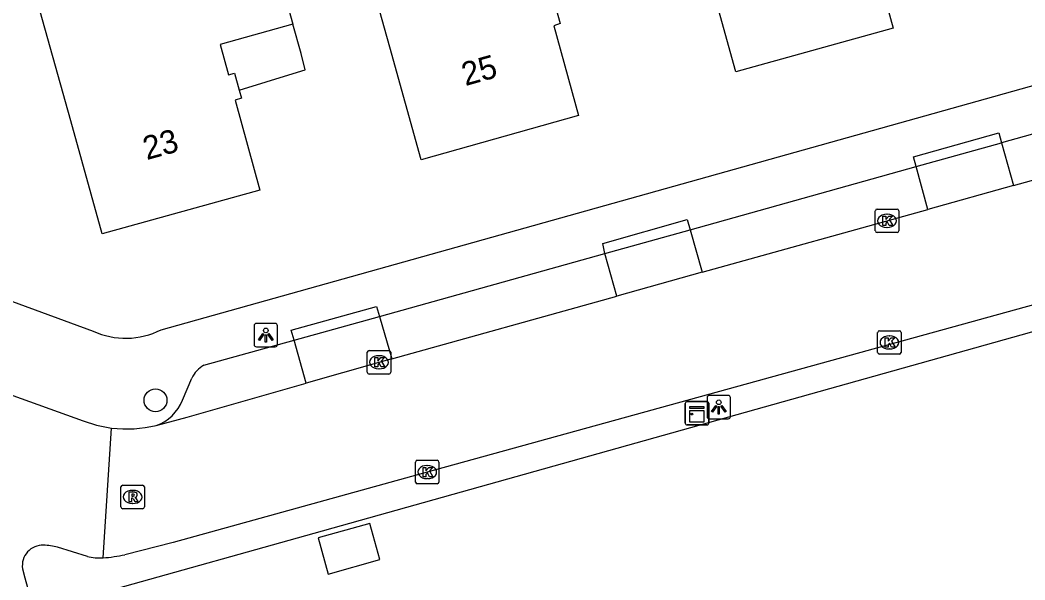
# Model space of a CAD drawing. Extents: x 159628 to 160723, y 388176 to 389416.
# Drawn here: x 159913.26 to 159956.19, y 388453.52 to 388477.42 of the extents above; entities that cross this region are included whole.
import ezdxf

# ---------------------------------------------------------------- set-up
doc = ezdxf.new("R2010")
doc.units = 0
for name, color, linetype in [('IMGEO_Boom', 7, 'Continuous'), ('IMGEO_Kast', 7, 'Continuous'), ('IMGEO_Kolk', 7, 'Continuous'), ('IMGEO_Lichtpunt', 7, 'Continuous'), ('IMGEO_Muur', 7, 'Continuous'), ('IMGEO_Pand', 7, 'Continuous'), ('IMGEO_Pand_nummerreeks', 7, 'Continuous'), ('IMGEO_Pand_overbouw', 7, 'Continuous'), ('IMGEO_Parkeervlak_open', 7, 'Continuous'), ('IMGEO_Rijbaan_lokaal_open', 7, 'Continuous'), ('IMGEO_Rioolput', 7, 'Continuous'), ('IMGEO_Voetpad_open', 7, 'Continuous')]:
    doc.layers.add(name, color=color, linetype=linetype)

msp = doc.modelspace()

# ---------------------------------------------------------------- linework, layer by layer
at = {"layer": 'IMGEO_Boom'}
msp.add_circle((159919.046, 388461.193), 0.489, dxfattribs=at)
at = {"layer": 'IMGEO_Kast'}
for p, q in [((159941.683, 388460.213), (159941.683, 388461.054)), ((159941.683, 388461.054), (159941.683, 388460.213)), ((159941.758, 388461.138), (159942.599, 388461.138)), ((159942.599, 388461.138), (159941.758, 388461.138)), ((159942.683, 388461.063), (159942.683, 388460.222)), ((159942.683, 388460.222), (159942.683, 388461.063)), ((159942.608, 388460.138), (159941.767, 388460.138)), ((159941.767, 388460.138), (159942.608, 388460.138))]:
    msp.add_line(p, q, dxfattribs=at)
for points in [[(159941.878, 388460.928), (159942.478, 388460.928), (159942.478, 388460.843), (159941.878, 388460.843), (159941.878, 388460.928)], [(159941.878, 388460.753), (159942.478, 388460.753), (159942.478, 388460.264), (159941.878, 388460.264), (159941.878, 388460.753)]]:
    msp.add_lwpolyline(points, dxfattribs=at)
msp.add_circle((159941.962, 388460.602), 0.0377, dxfattribs=at)
for centre, start, end in [((159941.761, 388461.06), 92.4484, 184.2845), ((159941.761, 388461.06), 92.4484, 184.2845), ((159942.605, 388461.06), 2.4484, 94.2845), ((159942.605, 388461.06), 2.4484, 94.2845), ((159941.761, 388460.216), 182.4484, 274.2845), ((159941.761, 388460.216), 182.4484, 274.2845), ((159942.605, 388460.216), 272.4484, 4.2845), ((159942.605, 388460.216), 272.4484, 4.2845)]:
    msp.add_arc(centre, 0.0779, start, end, dxfattribs=at)
at = {"layer": 'IMGEO_Kolk'}
for p, q in [((159949.876, 388469.354), (159950.728, 388469.354)), ((159949.801, 388468.428), (159949.801, 388469.28)), ((159950.289, 388469.134), (159950.314, 388469.134)), ((159950.802, 388469.28), (159950.802, 388468.428)), ((159950.312, 388468.574), (159950.287, 388468.574)), ((159950.728, 388468.354), (159949.876, 388468.354)), ((159949.901, 388463.237), (159949.901, 388464.089)), ((159949.976, 388464.163), (159950.828, 388464.163)), ((159950.389, 388463.943), (159950.414, 388463.943)), ((159950.902, 388464.089), (159950.902, 388463.237)), ((159950.412, 388463.383), (159950.387, 388463.383)), ((159928.095, 388462.387), (159928.095, 388463.239)), ((159928.17, 388463.313), (159929.022, 388463.313)), ((159928.583, 388463.093), (159928.608, 388463.093)), ((159929.096, 388463.239), (159929.096, 388462.387)), ((159950.828, 388463.163), (159949.976, 388463.163)), ((159928.606, 388462.533), (159928.581, 388462.533)), ((159929.022, 388462.313), (159928.17, 388462.313)), ((159930.232, 388458.629), (159931.084, 388458.629)), ((159930.157, 388457.703), (159930.157, 388458.555)), ((159930.645, 388458.409), (159930.67, 388458.409)), ((159931.158, 388458.555), (159931.158, 388457.703)), ((159930.668, 388457.849), (159930.643, 388457.849)), ((159931.084, 388457.629), (159930.232, 388457.629))]:
    msp.add_line(p, q, dxfattribs=at)
for points in [[(159949.876, 388469.354), (159950.728, 388469.354)], [(159949.801, 388468.428), (159949.801, 388469.28)], [(159950.122, 388469.054), (159950.245, 388469.054), (159950.245, 388468.903), (159950.375, 388469.054), (159950.539, 388469.054), (159950.393, 388468.903), (159950.546, 388468.654), (159950.394, 388468.654), (159950.309, 388468.818), (159950.245, 388468.751), (159950.245, 388468.654), (159950.122, 388468.654), (159950.122, 388469.054)], [(159950.802, 388469.28), (159950.802, 388468.428)], [(159950.728, 388468.354), (159949.876, 388468.354)], [(159949.901, 388463.237), (159949.901, 388464.089)], [(159949.976, 388464.163), (159950.828, 388464.163)], [(159950.222, 388463.863), (159950.345, 388463.863), (159950.345, 388463.712), (159950.475, 388463.863), (159950.639, 388463.863), (159950.493, 388463.712), (159950.646, 388463.463), (159950.494, 388463.463), (159950.409, 388463.627), (159950.345, 388463.56), (159950.345, 388463.463), (159950.222, 388463.463), (159950.222, 388463.863)], [(159950.902, 388464.089), (159950.902, 388463.237)], [(159928.095, 388462.387), (159928.095, 388463.239)], [(159928.17, 388463.313), (159929.022, 388463.313)], [(159928.416, 388463.013), (159928.539, 388463.013), (159928.539, 388462.862), (159928.669, 388463.013), (159928.833, 388463.013), (159928.687, 388462.862), (159928.84, 388462.613), (159928.688, 388462.613), (159928.603, 388462.777), (159928.539, 388462.71), (159928.539, 388462.613), (159928.416, 388462.613), (159928.416, 388463.013)], [(159929.096, 388463.239), (159929.096, 388462.387)], [(159950.828, 388463.163), (159949.976, 388463.163)], [(159929.022, 388462.313), (159928.17, 388462.313)], [(159930.232, 388458.629), (159931.084, 388458.629)], [(159930.157, 388457.703), (159930.157, 388458.555)], [(159930.478, 388458.329), (159930.601, 388458.329), (159930.601, 388458.178), (159930.731, 388458.329), (159930.895, 388458.329), (159930.749, 388458.178), (159930.902, 388457.929), (159930.75, 388457.929), (159930.665, 388458.093), (159930.601, 388458.026), (159930.601, 388457.929), (159930.478, 388457.929), (159930.478, 388458.329)], [(159931.158, 388458.555), (159931.158, 388457.703)], [(159931.084, 388457.629), (159930.232, 388457.629)]]:
    msp.add_lwpolyline(points, dxfattribs=at)
for centre, start, end in [((159949.878, 388469.278), 91.552, 178.448), ((159949.878, 388469.278), 91.552, 178.448), ((159950.726, 388469.278), 1.552, 88.448), ((159950.726, 388469.278), 1.552, 88.448), ((159949.878, 388468.43), 181.552, 268.448), ((159949.878, 388468.43), 181.552, 268.448), ((159950.726, 388468.43), 271.552, 358.448), ((159950.726, 388468.43), 271.552, 358.448), ((159949.978, 388464.087), 91.552, 178.448), ((159949.978, 388464.087), 91.552, 178.448), ((159950.826, 388464.087), 1.552, 88.448), ((159950.826, 388464.087), 1.552, 88.448), ((159928.172, 388463.237), 91.552, 178.448), ((159928.172, 388463.237), 91.552, 178.448), ((159929.02, 388463.237), 1.552, 88.448), ((159929.02, 388463.237), 1.552, 88.448), ((159949.978, 388463.239), 181.552, 268.448), ((159949.978, 388463.239), 181.552, 268.448), ((159950.826, 388463.239), 271.552, 358.448), ((159950.826, 388463.239), 271.552, 358.448), ((159928.172, 388462.389), 181.552, 268.448), ((159928.172, 388462.389), 181.552, 268.448), ((159929.02, 388462.389), 271.552, 358.448), ((159929.02, 388462.389), 271.552, 358.448), ((159930.234, 388458.553), 91.552, 178.448), ((159930.234, 388458.553), 91.552, 178.448), ((159931.082, 388458.553), 1.552, 88.448), ((159931.082, 388458.553), 1.552, 88.448), ((159930.234, 388457.705), 181.552, 268.448), ((159930.234, 388457.705), 181.552, 268.448), ((159931.082, 388457.705), 271.552, 358.448), ((159931.082, 388457.705), 271.552, 358.448)]:
    msp.add_arc(centre, 0.0765, start, end, dxfattribs=at)
for centre, major_axis, ratio, start_param, end_param in [((159950.288, 388468.854), (-0.387, 0.002), 0.722429, 4.712389, 7.853982), ((159950.313, 388468.854), (-0.39, 0.002), 0.717154, 1.570796, 4.712389), ((159950.388, 388463.663), (-0.387, 0.002), 0.722429, 4.712389, 7.853982), ((159950.413, 388463.663), (-0.39, 0.002), 0.717154, 1.570796, 4.712389), ((159928.582, 388462.813), (-0.387, 0.002), 0.722429, 4.712389, 7.853982), ((159928.607, 388462.813), (-0.39, 0.002), 0.717154, 1.570796, 4.712389), ((159930.644, 388458.129), (-0.387, 0.002), 0.722429, 4.712389, 7.853982), ((159930.669, 388458.129), (-0.39, 0.002), 0.717154, 1.570796, 4.712389)]:
    msp.add_ellipse(centre, major_axis=major_axis, ratio=ratio, start_param=start_param, end_param=end_param, dxfattribs=at)
at = {"layer": 'IMGEO_Lichtpunt'}
for p, q in [((159923.261, 388464.376), (159923.261, 388463.569)), ((159923.261, 388464.376), (159923.261, 388463.569)), ((159924.163, 388464.471), (159923.355, 388464.471)), ((159924.163, 388464.471), (159923.355, 388464.471)), ((159924.257, 388463.569), (159924.257, 388464.376)), ((159924.257, 388463.569), (159924.257, 388464.376)), ((159923.355, 388463.475), (159924.163, 388463.475)), ((159923.355, 388463.475), (159924.163, 388463.475)), ((159942.613, 388461.307), (159942.613, 388460.5)), ((159942.613, 388461.307), (159942.613, 388460.5)), ((159943.515, 388461.402), (159942.707, 388461.402)), ((159943.515, 388461.402), (159942.707, 388461.402)), ((159943.609, 388460.5), (159943.609, 388461.307)), ((159943.609, 388460.5), (159943.609, 388461.307)), ((159942.707, 388460.406), (159943.515, 388460.406)), ((159942.707, 388460.406), (159943.515, 388460.406))]:
    msp.add_line(p, q, dxfattribs=at)
for points in [[(159923.635, 388464.04), (159923.674, 388464.012), (159923.486, 388463.75), (159923.448, 388463.777), (159923.635, 388464.04)], [(159923.737, 388463.992), (159923.784, 388463.992), (159923.784, 388463.67), (159923.737, 388463.67), (159923.737, 388463.992)], [(159923.847, 388464.012), (159923.885, 388464.039), (159924.072, 388463.777), (159924.033, 388463.749), (159923.847, 388464.012)], [(159942.987, 388460.971), (159943.026, 388460.943), (159942.838, 388460.681), (159942.8, 388460.708), (159942.987, 388460.971)], [(159943.089, 388460.923), (159943.136, 388460.923), (159943.136, 388460.601), (159943.089, 388460.601), (159943.089, 388460.923)], [(159943.199, 388460.943), (159943.237, 388460.97), (159943.424, 388460.708), (159943.385, 388460.68), (159943.199, 388460.943)]]:
    msp.add_lwpolyline(points, dxfattribs=at)
for centre in [(159923.76, 388464.174), (159943.112, 388461.105)]:
    msp.add_circle(centre, 0.0994, dxfattribs=at)
for centre, start, end in [((159923.355, 388464.376), 90, 180), ((159923.355, 388464.376), 90, 180), ((159924.163, 388464.376), 0, 90), ((159924.163, 388464.376), 0, 90), ((159923.355, 388463.569), 180, 270), ((159923.355, 388463.569), 180, 270), ((159924.163, 388463.569), 270, 0), ((159924.163, 388463.569), 270, 360), ((159942.707, 388461.307), 90, 180), ((159942.707, 388461.307), 90, 180), ((159943.515, 388461.307), 0, 90), ((159943.515, 388461.307), 0, 90), ((159942.707, 388460.5), 180, 270), ((159942.707, 388460.5), 180, 270), ((159943.515, 388460.5), 270, 0), ((159943.515, 388460.5), 270, 360)]:
    msp.add_arc(centre, 0.0946, start, end, dxfattribs=at)
at = {"layer": 'IMGEO_Muur'}
msp.add_lwpolyline([(159925.832, 388455.524), (159959.997, 388465.092)], dxfattribs=at)
at = {"layer": 'IMGEO_Pand'}
for points in [[(159950.64, 388488.978), (159951.972, 388484.158), (159948.858, 388483.298), (159949.217, 388481.996), (159949.477, 388482.067), (159949.678, 388481.342), (159949.772, 388481.002), (159949.508, 388480.912), (159950.557, 388477.077), (159943.837, 388475.221), (159942.502, 388480.04), (159940.985, 388485.514), (159944.105, 388486.378), (159942.931, 388490.615), (159949.672, 388492.483), (159950.64, 388488.978)], [(159938.532, 388480.412), (159935.434, 388479.557), (159935.793, 388478.255), (159936.053, 388478.326), (159936.243, 388477.64), (159936.342, 388477.283), (159936.058, 388477.184), (159937.126, 388473.343), (159930.4, 388471.458), (159929.055, 388476.274), (159927.523, 388481.761), (159930.649, 388482.634), (159929.467, 388486.866), (159936.2, 388488.746), (159937.184, 388485.228), (159938.532, 388480.412)], [(159923.574, 388482.06), (159924.919, 388477.244), (159921.805, 388476.384), (159922.164, 388475.082), (159922.424, 388475.153), (159922.625, 388474.428), (159922.719, 388474.088), (159922.455, 388473.998), (159923.504, 388470.163), (159916.769, 388468.303), (159915.425, 388473.12), (159913.89, 388478.62), (159917.021, 388479.496), (159915.84, 388483.716), (159922.584, 388485.604), (159923.574, 388482.06)], [(159925.991, 388455.313), (159926.424, 388453.769), (159928.635, 388454.389), (159928.202, 388455.933), (159925.991, 388455.313)]]:
    msp.add_lwpolyline(points, dxfattribs=at)
at = {"layer": 'IMGEO_Pand_overbouw'}
msp.add_lwpolyline([(159922.625, 388474.428), (159924.925, 388475.148), (159925.435, 388475.298), (159925.263, 388475.998), (159924.919, 388477.244), (159921.805, 388476.384), (159922.164, 388475.082), (159922.424, 388475.153)], close=True, dxfattribs=at)
at = {"layer": 'IMGEO_Parkeervlak_open'}
for points in [[(159955.198, 388472.186), (159955.708, 388470.358)], [(159952.05, 388469.34), (159951.542, 388471.166)], [(159941.895, 388468.474), (159942.401, 388466.655)], [(159938.754, 388465.64), (159938.248, 388467.459)], [(159928.622, 388464.774), (159929.138, 388462.964)], [(159925.486, 388461.926), (159924.964, 388463.756)]]:
    msp.add_lwpolyline(points, dxfattribs=at)
at = {"layer": 'IMGEO_Rijbaan_lokaal_open'}
for points in [[(159955.708, 388470.358), (159962.432, 388472.229)], [(159955.708, 388470.358), (159952.05, 388469.34)], [(159942.401, 388466.655), (159952.05, 388469.34)], [(159963.841, 388467.276), (159930.654, 388458.13), (159919.806, 388455.118), (159917.73, 388454.597)], [(159942.401, 388466.655), (159938.754, 388465.64)], [(159929.138, 388462.964), (159938.754, 388465.64)], [(159909.074, 388462.915), (159909.569, 388462.607), (159915.949, 388460.312), (159916.527, 388460.133), (159917.172, 388460.006)], [(159929.138, 388462.964), (159928.592, 388462.812), (159925.486, 388461.926)], [(159919.075, 388460.117), (159920.394, 388460.474), (159925.486, 388461.926)], [(159916.812, 388454.464), (159917.172, 388460.006)], [(159916.136, 388454.528), (159914.865, 388454.92)], [(159913.366, 388454.001), (159913.457, 388453.607), (159913.858, 388452.179)]]:
    msp.add_lwpolyline(points, dxfattribs=at)
for centre, radius, start, end in [((159917.813, 388465.378), 5.41, 263.1913, 283.4852), ((159914.218, 388454.142), 0.863, 87.0578, 189.3921), ((159914.138, 388451.907), 3.099, 76.4326, 87.7064), ((159916.671, 388456.579), 2.12, 255.3755, 273.8079), ((159916.141, 388462.329), 7.894, 274.8754, 281.6119)]:
    msp.add_arc(centre, radius, start, end, dxfattribs=at)
at = {"layer": 'IMGEO_Rioolput'}
for p, q in [((159917.57, 388456.638), (159917.57, 388457.49)), ((159917.645, 388457.564), (159918.497, 388457.564)), ((159918.058, 388457.344), (159918.083, 388457.344)), ((159918.571, 388457.49), (159918.571, 388456.638)), ((159918.497, 388456.564), (159917.645, 388456.564)), ((159918.081, 388456.784), (159918.056, 388456.784))]:
    msp.add_line(p, q, dxfattribs=at)
for points in [[(159917.57, 388456.638), (159917.57, 388457.49)], [(159917.645, 388457.564), (159918.497, 388457.564)], [(159918.571, 388457.49), (159918.571, 388456.638)], [(159918.159, 388457.262), (159917.907, 388457.264), (159917.907, 388456.864)], [(159917.907, 388456.864), (159918.031, 388456.864), (159918.031, 388457.026), (159918.042, 388457.026)], [(159918.085, 388457.183), (159918.031, 388457.183), (159918.031, 388457.102)], [(159918.031, 388457.102), (159918.083, 388457.102)], [(159918.089, 388456.997), (159918.16, 388456.864), (159918.3, 388456.864), (159918.235, 388456.99)], [(159918.497, 388456.564), (159917.645, 388456.564)]]:
    msp.add_lwpolyline(points, dxfattribs=at)
for centre, radius, start, end in [((159917.647, 388457.488), 0.0765, 91.552, 178.448), ((159917.647, 388457.488), 0.0765, 91.552, 178.448), ((159918.495, 388457.488), 0.0765, 1.552, 88.448), ((159918.495, 388457.488), 0.0765, 1.552, 88.448), ((159918.041, 388456.973), 0.0533, 26.0293, 88.6989), ((159918.067, 388457.291), 0.19, 274.7715, 282.9687), ((159918.091, 388457.087), 0.0964, 77.0061, 93.1865), ((159918.105, 388457.144), 0.0378, 276.6634, 79.6772), ((159918.158, 388457.152), 0.109, 350.3612, 89.416), ((159918.156, 388457.152), 0.112, 277.5842, 350.9817), ((159918.14, 388456.937), 0.108, 29.5134, 73.7905), ((159917.647, 388456.64), 0.0765, 181.552, 268.448), ((159917.647, 388456.64), 0.0765, 181.552, 268.448), ((159918.495, 388456.64), 0.0765, 271.552, 358.448), ((159918.495, 388456.64), 0.0765, 271.552, 358.448)]:
    msp.add_arc(centre, radius, start, end, dxfattribs=at)
for centre, major_axis, ratio, start_param, end_param in [((159918.057, 388457.064), (-0.387, 0.002), 0.722429, 4.712389, 7.853982), ((159918.082, 388457.064), (-0.39, 0.002), 0.717154, 1.570796, 4.712389)]:
    msp.add_ellipse(centre, major_axis=major_axis, ratio=ratio, start_param=start_param, end_param=end_param, dxfattribs=at)
at = {"layer": 'IMGEO_Voetpad_open'}
for points in [[(159919.282, 388464.204), (159968.634, 388478.015)], [(159961.006, 388473.807), (159955.198, 388472.186)], [(159951.542, 388471.166), (159951.43, 388471.586), (159955.084, 388472.604), (159955.198, 388472.186)], [(159951.542, 388471.166), (159955.198, 388472.186)], [(159941.895, 388468.474), (159951.542, 388471.166)], [(159899.675, 388470.27), (159916.381, 388464.148)], [(159938.248, 388467.459), (159938.152, 388467.887), (159941.769, 388468.908), (159941.895, 388468.474)], [(159917.375, 388453.156), (159925.832, 388455.524), (159959.997, 388465.092), (159972.097, 388468.48)], [(159938.248, 388467.459), (159941.895, 388468.474)], [(159928.622, 388464.774), (159938.248, 388467.459)], [(159924.964, 388463.756), (159924.847, 388464.181), (159928.483, 388465.197), (159928.622, 388464.774)], [(159924.964, 388463.756), (159928.622, 388464.774)], [(159921.113, 388462.685), (159924.964, 388463.756)], [(159920.194, 388461.203), (159920.601, 388462.137)]]:
    msp.add_lwpolyline(points, dxfattribs=at)
for centre, radius, start, end in [((159917.775, 388467.11), 3.273, 244.7967, 297.4151), ((159921.605, 388461.712), 1.09, 116.8247, 157.0656), ((159918.496, 388461.833), 1.811, 288.6385, 339.6467)]:
    msp.add_arc(centre, radius, start, end, dxfattribs=at)

# ---------------------------------------------------------------- texts
at = {"layer": 'IMGEO_Pand_nummerreeks'}
for s, rotation, p in [('25', 15.6558, (159932.287, 388474.604)), ('23', 15.4385, (159918.67, 388471.442))]:
    msp.add_text(s, height=1, rotation=rotation, dxfattribs=at).set_placement(p)

doc.saveas('drawing.dxf')
